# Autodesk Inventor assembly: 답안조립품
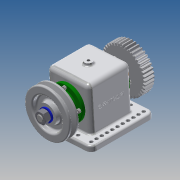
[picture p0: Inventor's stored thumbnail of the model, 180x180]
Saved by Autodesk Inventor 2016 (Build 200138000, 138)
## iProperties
Created: 2018-11
Part Number: 답안조립품
Document SubType Name: Assembly
Designer: Administrator
Author: Administrator
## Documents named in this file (13)
- Y:\481107V1004 홍진욱\481107V1004\답안조립품.iam
- Y:\481107V1004 홍진욱\481107V1004\V벨트풀리.ipt
- Y:\481107V1004 홍진욱\481107V1004\너트 M12x1.25.ipt
- Y:\481107V1004 홍진욱\481107V1004\베어링 6203.ipt
- Y:\481107V1004 홍진욱\481107V1004\볼트 M4.ipt
- Y:\481107V1004 홍진욱\481107V1004\부시.ipt
- Y:\481107V1004 홍진욱\481107V1004\부품1.ipt
- Y:\481107V1004 홍진욱\481107V1004\스퍼기어.ipt
- Y:\481107V1004 홍진욱\481107V1004\오일 실 26 38 8.ipt
- Y:\481107V1004 홍진욱\481107V1004\와셔 12x24.ipt
- Y:\481107V1004 홍진욱\481107V1004\축.ipt
- Y:\481107V1004 홍진욱\481107V1004\커버.ipt
- Y:\481107V1004 홍진욱\481107V1004\키 5x5x12.ipt
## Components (1 placed, 1 different names)
1. V벨트풀리:1
